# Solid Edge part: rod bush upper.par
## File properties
Author: Vicky Raina
Template: Normal.par
Last saved by: Robert a Rhodes jr
Revision: 2
Application: Solid Edge
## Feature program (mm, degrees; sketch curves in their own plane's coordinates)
sketch for "unnamed Protrusion 1" #1 plane through (0, 0, 0) normal (0, 0, 1) x-axis (1, 0, 0)
  circle centre (0, 0) radius 11
sketch for "unnamed Protrusion 1" #2 plane through (0, 0, 0) normal (0, 0, 1) x-axis (1, 0, 0)
  circle centre (0, 0) radius 12
extrude "unnamed Protrusion 1" add finite 42 along -normal
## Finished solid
Body 1: solid body, 4 faces, 4 edges, 0 vertices.
  Faces by surface: cylinder 2, plane 2
  Edges by curve: circle 4
Bounding box of the edges (mm): 24.000 x 24.000 x 42.000, from (-12, -12, -42) to (12, 12, 0).
Cylindrical faces by radius (mm): R11 x1, R12 x1
Planar faces by outward normal: +z 1, -z 1
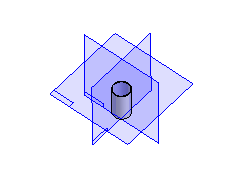
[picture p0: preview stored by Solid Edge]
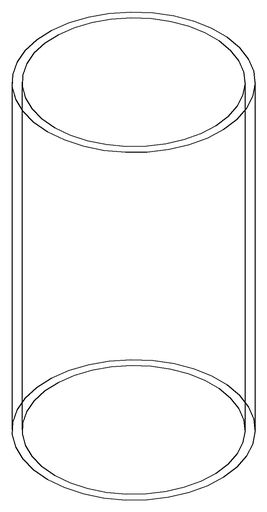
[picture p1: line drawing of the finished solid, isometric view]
